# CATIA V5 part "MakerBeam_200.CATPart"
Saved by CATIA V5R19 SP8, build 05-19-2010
Part number: Profilé Makebeam 200
Definition: Profilé Makebeam 200
Nomenclature: MakerBeam_100090
Bounding box of the stored display mesh (mm): x 0 to 200, y -5 to 5, z -5 to 5
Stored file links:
  D:\Documents\1_Travail\1 - ac-limoges.fr\ac-limoges.fr\Emmanuel Maynard - STI2D_Turgot\1 - IT-I2D\Activités_IT_Première\IT_3_Abris_bus\Maquettes numériques\Abribus_eleve\MakerBeam_200.CATPart
  C:\Program Files\Dassault Systemes\B19\win_b64\reffiles\standard\MetricThickPitch.txt
  D:\Documents\1_Travail\2- 2I2D\6 -  Ressources ITEC\Ressources Techniques\0-Maquettes numériques_Composants\Catalogue_Makeblock\Catalog_Makeblock\12_MakerBeam\TableMakerbeam.xls
  D:\Documents\1_Travail\2- 2I2D\6 -  Ressources ITEC\Ressources Techniques\0-Maquettes numériques_Composants\Catalogue_Makeblock\Catalog_Makeblock\12_MakerBeam\TableMakerbeam.txt
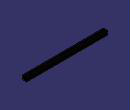
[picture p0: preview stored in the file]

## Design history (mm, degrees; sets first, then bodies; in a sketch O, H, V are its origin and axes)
Parameters
  Longueur = 200 mm
  `Désignation` = "Profilé Makebeam 200"
  `Référence` = "MakerBeam_100090"
AxisSystem1: origin (0, 0, 0), X (1, 0, 0), Y (0, 1, 0), Z (0, 0, 1)
Body1 (main body)
  Sketch1 on YZ plane of AxisSystem1, origin (0, 0, 0), H (0, 1, 0), V (0, 0, 1)
    line L1 (-5, 5) -> (-1.5, 5)
    point P1 (5, 5)
    point P2 (-5, 5)
    arc A1 centre (0, 0) radius 1.2 from (0, 1.2) to (-0.8485, 0.8485) ccw
    line L2 (-0.8485, 0.8485) -> (-5, 5)
    line L3 (0, 1.2) -> (0, 2)
    reference intersected line E1 through (0, 0) direction (-1, 0) from XY plane of AxisSystem1
    reference intersected line E2 through (0, 0) direction (0, 1) from ZX plane of AxisSystem1
    line L4 (-1.5, 5) -> (-1.5, 4)
    line L5 (-1.5, 4) -> (-3.2929, 4)
    line L6 (-3.2929, 4) -> (-1, 2)
    line L7 (-1, 2) -> (0, 2)
    reference projected line E3 through (0, 0) direction (0, 1) from edge [ZX plane of AxisSystem1 | YZ plane of AxisSystem1]
    radius A1 = 1.2
    distance L1 E1 = 5
    distance P2 E3 = 5
    distance L4 P2 = 3.5
    length L7 = 1
    distance L5 L1 = 1
    distance L7 L1 = 3
    angle L6 L3 = 48.903
    horizontal: L1 H, L5 H, L7 H
    vertical: L3 V, L4 V
    coincidence: L3 E2, L2 O
  Pad1: profile Sketch1, direction (1, 0, 0), length 200 {= Longueur}
  Fillet1: radius 0.2, on edge [face of Pad1 from Sketch1.L5 | face of Pad1 from Sketch1.L6]; edge [face of Pad1 from Sketch1.L6 | face of Pad1 from Sketch1.L7]; edge [face of Pad1 from Sketch1.L1 | face of Pad1 from Sketch1.L4]; edge [face of Pad1 from Sketch1.L4 | face of Pad1 from Sketch1.L5]
  Mirror1: of the body so far, about face of Pad1 from Sketch1.L2
  Fillet2: radius 0.2, on edge [face of Mirror1 | face of Pad1 from Sketch1.L1]
  Mirror2: of the body so far, about face of Mirror1
  Mirror3: of the body so far, about face of Pad1 from Sketch1.L3
  Sketch2 on face of Pad1, origin (200, 0.9666, 1.0824), H (0, 1, 0), V (0, 0, 1)
    point P1 (-0.9666, -1.0824)
    projected point E1 (-0.9666, -1.0824) from axis of face of Mirror3
    coincidence: E1 P1
  Hole1: placed by Sketch2, at (200, 0, 0) direction (-1, 0, 0), diameter 2.459, depth 10, threaded "M3", thread diameter 3, thread depth 8, pitch 0.5
  Sketch3 on face of Pad1, origin (0, -1.3866, 1.2369), H (0, 1, 0), V (0, 0, -1)
    point P1 (1.3866, 1.2369)
    reference projected point E1 (1.3866, 1.2369) from axis of face of Pad1
    coincidence: P1 E1
  Hole2: placed by Sketch3, at (0, 0, 0) direction (1, 0, 0), diameter 2.459, depth 10, threaded "M3", thread diameter 3, thread depth 8, pitch 0.5
Current feature: Mirror3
